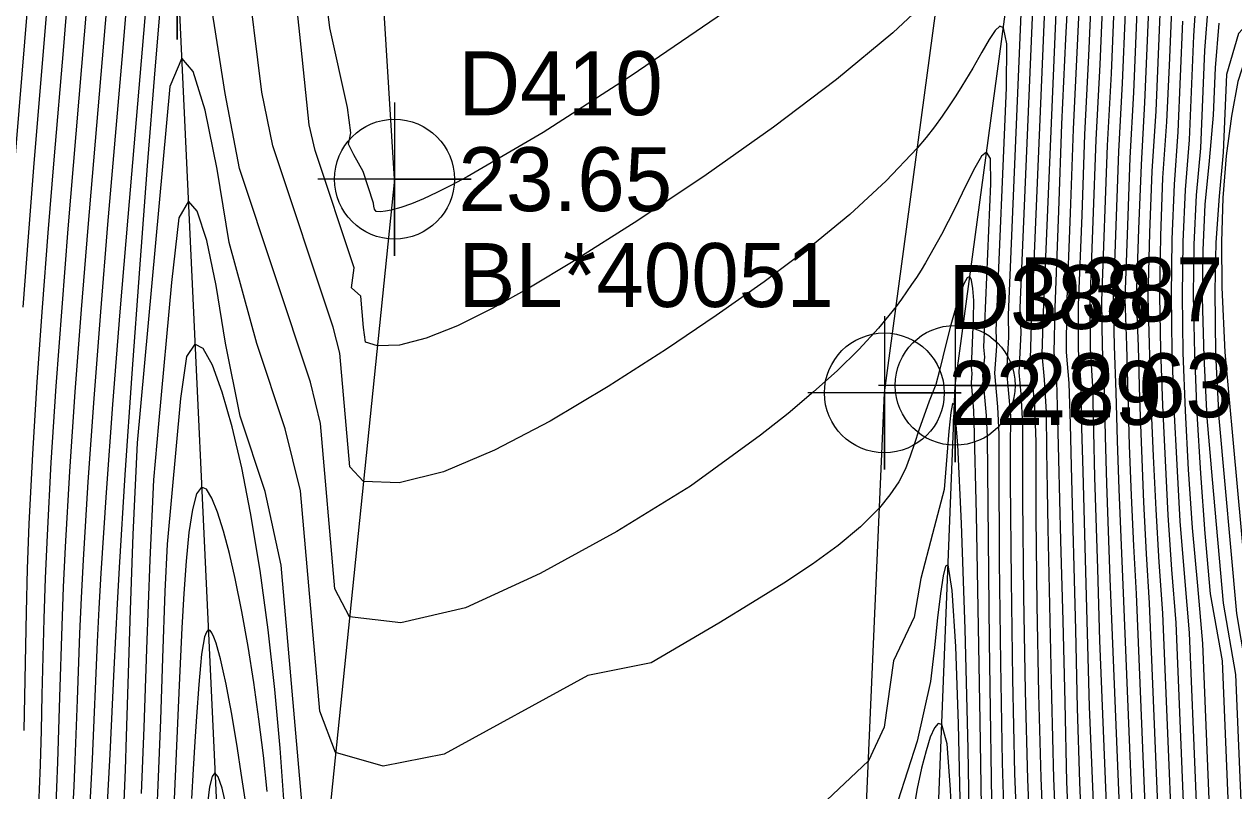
# Model space of a CAD drawing. Extents: x 2356077 to 2359823, y 225951 to 227822.
# Drawn here: x 2356540.32 to 2356587.63, y 227196.5 to 227226.48 of the extents above; entities that cross this region are included whole.
import ezdxf

# ---------------------------------------------------------------- set-up
doc = ezdxf.new("R2010")
doc.units = 0
for name, color, linetype in [('DTM Contours Major', 7, 'Continuous'), ('DTM Contours Minor', 7, 'Continuous'), ('Exist DTM Breakline', 7, 'Continuous'), ('Exist DTM Breakline Cogo Comment', 7, 'Continuous'), ('Exist DTM Breakline Cogo Elevation', 7, 'Continuous'), ('Exist DTM Breakline Cogo Number', 7, 'Continuous'), ('Exist DTM Breakline Cogo Point CELL', 7, 'Continuous'), ('Exist DTM Drainline', 7, 'Continuous'), ('Exist DTM Drainline Cogo Elevation', 7, 'Continuous'), ('Exist DTM Drainline Cogo Number', 7, 'Continuous'), ('Exist DTM Drainline Cogo Point CELL', 7, 'Continuous'), ('PH Exist DTM Breakline', 7, 'Continuous')]:
    doc.layers.add(name, color=color, linetype=linetype)

msp = doc.modelspace()

# ---------------------------------------------------------------- linework, layer by layer
at = {"layer": 'DTM Contours Major'}
for points in [[(2356580.928, 227233.104), (2356580.177, 227215.223), (2356580.125, 227213.572), (2356580.214, 227212.59), (2356580.285, 227211.313), (2356580.3, 227209.8), (2356580.324, 227208.284), (2356580.353, 227206.755), (2356580.499, 227200.164), (2356580.583, 227196.978), (2356580.991, 227187.051)], [(2356583.192, 227233.181), (2356582.829, 227224.549), (2356582.68, 227221.735), (2356582.456, 227215.663), (2356582.482, 227213.849), (2356582.554, 227212.198), (2356582.599, 227210.352), (2356582.655, 227208.511), (2356582.78, 227204.806), (2356583.105, 227196.834), (2356583.445, 227188.558)], [(2356542.236, 227230.325), (2356541.852, 227225.609), (2356541.482, 227221.178), (2356541.249, 227218.319), (2356541.023, 227215.406), (2356540.816, 227212.5), (2356540.639, 227209.659), (2356540.504, 227206.944), (2356540.439, 227205.177), (2356540.392, 227203.491), (2356540.301, 227198.856)], [(2356585.3, 227229.549), (2356585.103, 227224.873), (2356584.995, 227222.665), (2356584.843, 227220.469), (2356584.758, 227218.198), (2356584.725, 227215.861), (2356584.769, 227213.733), (2356584.841, 227211.577), (2356584.94, 227209.423), (2356585.056, 227207.276), (2356585.195, 227205.151), (2356585.364, 227203.073), (2356585.889, 227190.32)], [(2356578.194, 227194.317), (2356578.079, 227202.349), (2356578, 227210.342), (2356577.961, 227211.172), (2356577.818, 227212.745), (2356577.888, 227213.465), (2356577.859, 227213.854), (2356578.127, 227220.235), (2356578.109, 227221.233), (2356577.962, 227221.48), (2356577.765, 227221.326), (2356577.496, 227220.87), (2356577.149, 227220.168), (2356576.716, 227219.277), (2356576.192, 227218.252), (2356575.569, 227217.15), (2356575.396, 227216.865), (2356575.215, 227216.581), (2356575.028, 227216.295), (2356574.832, 227216.01), (2356574.629, 227215.726), (2356574.418, 227215.443), (2356573.727, 227214.597), (2356572.96, 227213.761), (2356572.115, 227212.93), (2356571.194, 227212.098), (2356570.196, 227211.259), (2356569.122, 227210.409), (2356566.384, 227208.411), (2356563.496, 227206.641), (2356560.499, 227204.994), (2356557.577, 227203.648), (2356555.054, 227203.071), (2356553.044, 227203.3), (2356552.465, 227204.402), (2356551.902, 227210.868), (2356551.518, 227212.478), (2356548.742, 227220.835), (2356548.174, 227223.77), (2356547.761, 227226.437), (2356547.379, 227228.812)], [(2356545.705, 227227.988), (2356545.434, 227224.703), (2356545.134, 227220.944), (2356544.825, 227216.915), (2356544.526, 227212.818), (2356544.255, 227208.855), (2356544.031, 227205.228), (2356543.953, 227203.815), (2356543.825, 227201.254), (2356543.668, 227197.932), (2356543.555, 227195.776)], [(2356589.008, 227227.424), (2356587.813, 227226.121), (2356587.349, 227224.513), (2356587.22, 227221.462), (2356587.053, 227219.76), (2356586.932, 227217.945), (2356586.884, 227216.067), (2356586.915, 227213.59), (2356587.041, 227211.067), (2356587.733, 227203.437), (2356588.228, 227200.499), (2356588.6, 227191.455)], [(2356548.957, 227196.169), (2356548.807, 227197.187), (2356548.656, 227198.158), (2356548.434, 227199.492), (2356548.323, 227200.105), (2356548.214, 227200.675), (2356548.105, 227201.194), (2356547.998, 227201.657), (2356547.91, 227201.991), (2356547.825, 227202.276), (2356547.742, 227202.506), (2356547.663, 227202.673), (2356547.588, 227202.77), (2356547.519, 227202.791), (2356547.443, 227202.708), (2356547.375, 227202.515), (2356547.314, 227202.223), (2356547.26, 227201.846), (2356547.209, 227201.396), (2356547.144, 227200.658), (2356547.054, 227199.41), (2356546.992, 227198.421), (2356546.929, 227197.348), (2356546.867, 227196.192)]]:
    msp.add_lwpolyline(points, dxfattribs=at)
at = {"layer": 'DTM Contours Minor'}
for points in [[(2356543.852, 227277.663), (2356543.291, 227273.755), (2356543.014, 227271.748), (2356542.749, 227269.703), (2356542.433, 227267.059), (2356542.174, 227264.669), (2356541.931, 227262.153), (2356541.716, 227259.564), (2356541.544, 227256.956), (2356541.428, 227254.385), (2356541.357, 227252.459), (2356541.365, 227250.684), (2356541.366, 227248.9), (2356541.392, 227243.756), (2356541.312, 227240.643), (2356541.253, 227239.098), (2356541.179, 227237.55), (2356541.09, 227235.992), (2356540.99, 227234.415), (2356540.865, 227232.636), (2356540.729, 227230.819), (2356540.429, 227227.059), (2356539.894, 227220.582)], [(2356580.51, 227233.908), (2356579.704, 227214.729), (2356579.664, 227213.409), (2356579.833, 227211.541), (2356579.883, 227210.149), (2356579.881, 227208.688), (2356579.888, 227207.219), (2356579.929, 227203.76), (2356579.986, 227200.289), (2356580.078, 227197.009), (2356580.5, 227186.773)], [(2356582.767, 227233.846), (2356582.392, 227224.908), (2356582.236, 227221.955), (2356582.001, 227215.592), (2356582.01, 227213.794), (2356582.099, 227212.312), (2356582.137, 227210.533), (2356582.186, 227208.76), (2356582.298, 227205.185), (2356582.377, 227202.383), (2356582.716, 227194.055)], [(2356583.614, 227232.485), (2356583.266, 227224.176), (2356583.125, 227221.498), (2356582.91, 227215.705), (2356582.955, 227213.886), (2356583.017, 227212.095), (2356583.07, 227210.192), (2356583.135, 227208.298), (2356583.206, 227206.404), (2356583.29, 227204.56), (2356583.933, 227188.937)], [(2356584.036, 227231.768), (2356583.702, 227223.811), (2356583.567, 227221.257), (2356583.467, 227218.612), (2356583.363, 227215.74), (2356583.429, 227213.909), (2356583.481, 227211.97), (2356583.544, 227210.002), (2356583.62, 227208.042), (2356583.702, 227206.085), (2356583.808, 227204.203), (2356584.422, 227189.273)], [(2356580.009, 227186.476), (2356579.577, 227196.955), (2356579.478, 227200.394), (2356579.418, 227204.114), (2356579.382, 227207.889), (2356579.379, 227209.345), (2356579.383, 227210.805), (2356579.313, 227212.026), (2356579.237, 227212.862), (2356579.307, 227214.412), (2356579.28, 227215.387), (2356579.938, 227231.057)], [(2356584.457, 227231.023), (2356584.138, 227223.423), (2356584.001, 227220.986), (2356583.907, 227218.469), (2356583.817, 227215.768), (2356583.892, 227213.875), (2356583.942, 227211.835), (2356584.016, 227209.806), (2356584.104, 227207.784), (2356584.197, 227205.767), (2356584.326, 227203.836), (2356584.912, 227189.617)], [(2356545.295, 227229.862), (2356544.983, 227226.121), (2356544.372, 227218.936), (2356544.065, 227215.236), (2356543.777, 227211.61), (2356543.523, 227208.164), (2356543.318, 227205.007), (2356543.241, 227203.622), (2356543.177, 227202.319), (2356542.978, 227197.74), (2356542.878, 227195.731)], [(2356567.705, 227226.948), (2356564.062, 227224.463), (2356560.611, 227222.25), (2356557.64, 227220.511), (2356557.028, 227220.185), (2356556.461, 227219.9), (2356555.941, 227219.657), (2356555.47, 227219.46), (2356555.048, 227219.309), (2356554.677, 227219.207), (2356554.457, 227219.166), (2356554.258, 227219.147), (2356554.086, 227219.154), (2356554.026, 227219.245), (2356553.996, 227219.359), (2356553.98, 227219.486), (2356553.571, 227220.719), (2356553.217, 227221.374), (2356553.003, 227221.793), (2356553.093, 227222.235), (2356552.961, 227223.221), (2356552.273, 227226.346), (2356551.833, 227229.926)], [(2356544.504, 227229.482), (2356544.135, 227225.107), (2356543.583, 227218.646), (2356543.302, 227215.237), (2356543.038, 227211.847), (2356542.806, 227208.58), (2356542.621, 227205.538), (2356542.546, 227204.051), (2356542.484, 227202.647), (2356542.387, 227200.053), (2356542.299, 227197.686), (2356542.255, 227196.685), (2356542.207, 227195.706)], [(2356581.211, 227229.087), (2356581.047, 227225.915), (2356580.892, 227222.576), (2356580.776, 227219.176), (2356580.636, 227215.387), (2356580.596, 227213.637), (2356580.696, 227212.532), (2356580.74, 227211.041), (2356580.772, 227209.47), (2356580.854, 227206.293), (2356580.942, 227203.142), (2356581.021, 227199.95), (2356581.091, 227196.85), (2356581.485, 227187.293)], [(2356578.699, 227193.831), (2356578.578, 227197.59), (2356578.513, 227201.501), (2356578.463, 227205.467), (2356578.448, 227209.367), (2356578.454, 227210.453), (2356578.406, 227211.519), (2356578.287, 227212.834), (2356578.362, 227213.893), (2356578.339, 227214.508), (2356578.737, 227223.991), (2356578.759, 227225.709), (2356578.619, 227226.345), (2356578.481, 227226.402), (2356578.298, 227226.239), (2356578.063, 227225.89), (2356577.771, 227225.387), (2356577.417, 227224.764), (2356576.997, 227224.053), (2356576.76, 227223.674), (2356576.503, 227223.283), (2356576.225, 227222.882), (2356575.924, 227222.473), (2356575.6, 227222.057), (2356575.251, 227221.637), (2356574.038, 227220.35), (2356572.614, 227219.045), (2356571.009, 227217.727), (2356569.257, 227216.405), (2356567.389, 227215.084), (2356565.437, 227213.77), (2356563.157, 227212.306), (2356560.891, 227210.956), (2356558.72, 227209.815), (2356556.725, 227208.979), (2356554.988, 227208.543), (2356553.589, 227208.602), (2356553.056, 227209.173), (2356552.67, 227213.609), (2356552.399, 227214.632), (2356550.043, 227221.725), (2356549.615, 227223.829), (2356549.006, 227228.786)], [(2356581.646, 227228.666), (2356581.346, 227222.377), (2356581.235, 227219.097), (2356581.088, 227215.386), (2356581.07, 227213.654), (2356581.181, 227212.438), (2356581.224, 227210.832), (2356581.263, 227209.182), (2356581.439, 227202.799), (2356581.504, 227199.725), (2356581.595, 227196.839), (2356581.977, 227187.557)], [(2356582.079, 227228.209), (2356581.949, 227225.25), (2356581.791, 227222.162), (2356581.681, 227219.015), (2356581.545, 227215.499), (2356581.54, 227213.73), (2356581.644, 227212.41), (2356581.677, 227210.698), (2356581.72, 227208.993), (2356581.82, 227205.554), (2356581.977, 227199.785), (2356582.465, 227187.927)], [(2356586.184, 227228.048), (2356586.056, 227226.03), (2356585.885, 227221.963), (2356585.73, 227220.005), (2356585.635, 227217.971), (2356585.606, 227215.872), (2356585.641, 227213.628), (2356585.727, 227211.354), (2356585.85, 227209.069), (2356586, 227206.788), (2356586.206, 227204.511), (2356586.404, 227202.264), (2356586.866, 227191.037)], [(2356576.084, 227227.831), (2356574.29, 227226.142), (2356572.096, 227224.325), (2356569.622, 227222.45), (2356566.99, 227220.584), (2356564.32, 227218.799), (2356561.731, 227217.163), (2356560.126, 227216.202), (2356558.629, 227215.367), (2356557.261, 227214.689), (2356556.042, 227214.199), (2356554.993, 227213.927), (2356554.133, 227213.904), (2356553.669, 227214.042), (2356553.588, 227214.616), (2356553.481, 227215.839), (2356553.119, 227216.175), (2356553.224, 227216.957), (2356551.702, 227221.537), (2356551.464, 227222.551), (2356551.154, 227225.581), (2356550.981, 227227.187)], [(2356579.513, 227186.285), (2356579.065, 227197.174), (2356578.987, 227200.882), (2356578.929, 227204.733), (2356578.899, 227208.593), (2356578.899, 227209.882), (2356578.905, 227211.165), (2356578.822, 227212.178), (2356578.758, 227212.887), (2356578.831, 227214.242), (2356578.816, 227215.111), (2356579.35, 227227.833)], [(2356584.776, 227227.851), (2356584.576, 227223.075), (2356584.427, 227220.734), (2356584.334, 227218.324), (2356584.27, 227215.807), (2356584.39, 227211.681), (2356584.477, 227209.59), (2356584.578, 227207.507), (2356584.692, 227205.443), (2356584.845, 227203.452), (2356585.4, 227189.965)], [(2356542.763, 227227.301), (2356542.028, 227218.472), (2356541.785, 227215.396), (2356541.559, 227212.326), (2356541.364, 227209.335), (2356541.213, 227206.5), (2356541.143, 227204.817), (2356541.091, 227203.219), (2356541.015, 227200.246), (2356540.981, 227198.855), (2356540.942, 227197.518), (2356540.906, 227196.553), (2356540.865, 227195.607), (2356540.818, 227194.67), (2356540.765, 227193.737), (2356540.706, 227192.799), (2356540.64, 227191.848), (2356540.434, 227189.167), (2356540.324, 227187.761), (2356540.216, 227186.305)], [(2356541.208, 227227.152), (2356540.688, 227220.881), (2356540.47, 227218.164), (2356540.261, 227215.41)], [(2356543.533, 227227.119), (2356542.805, 227218.528), (2356542.545, 227215.319), (2356542.302, 227212.107), (2356542.088, 227208.985), (2356541.92, 227206.046), (2356541.847, 227204.457), (2356541.789, 227202.953), (2356541.702, 227200.164), (2356541.62, 227197.612), (2356541.581, 227196.628), (2356541.537, 227195.664)], [(2356586.63, 227227.301), (2356586.484, 227225.451), (2356586.324, 227221.636), (2356586.162, 227219.792), (2356586.068, 227217.871), (2356586.043, 227215.879), (2356586.087, 227213.592), (2356586.19, 227211.259), (2356586.334, 227208.906), (2356586.499, 227206.559), (2356586.71, 227204.205), (2356587.177, 227201.583), (2356587.621, 227190.795)], [(2356585.628, 227226.598), (2356585.446, 227222.275), (2356585.297, 227220.209), (2356585.203, 227218.069), (2356585.176, 227215.87), (2356585.208, 227213.678), (2356585.286, 227211.468), (2356585.396, 227209.251), (2356585.525, 227207.039), (2356585.699, 227204.844), (2356585.883, 227202.68), (2356586.378, 227190.677)], [(2356587.04, 227226.516), (2356586.907, 227224.774), (2356586.829, 227222.918), (2356586.664, 227221.139), (2356586.498, 227219.431), (2356586.413, 227217.642), (2356586.398, 227215.777), (2356586.457, 227213.466), (2356586.581, 227211.092), (2356586.781, 227208.68), (2356587.22, 227203.836), (2356587.702, 227201.041), (2356588.11, 227191.125)], [(2356588.735, 227226.81), (2356588.262, 227225.693), (2356587.789, 227224.237), (2356587.541, 227222.884), (2356587.331, 227221.329), (2356587.205, 227219.688), (2356587.153, 227217.971), (2356587.162, 227216.187), (2356587.282, 227213.652), (2356588.238, 227203.117), (2356588.753, 227199.957), (2356589.09, 227191.785)], [(2356577.774, 227195.042), (2356577.711, 227199.219), (2356577.568, 227207.321), (2356577.472, 227210.939), (2356577.467, 227211.358), (2356577.367, 227212.472), (2356577.4, 227212.824), (2356577.375, 227213.086), (2356577.453, 227214.947), (2356577.456, 227215.669), (2356577.424, 227216.15), (2356577.376, 227216.469), (2356577.306, 227216.614), (2356577.2, 227216.567), (2356577.068, 227216.322), (2356576.914, 227215.912), (2356576.745, 227215.368), (2356576.566, 227214.722), (2356576.382, 227214.005), (2356576.121, 227212.94), (2356575.981, 227212.389), (2356575.717, 227211.737), (2356575.308, 227210.6), (2356575.141, 227210.084), (2356574.973, 227209.583), (2356574.786, 227209.09), (2356574.523, 227208.584), (2356574.174, 227208.071), (2356573.768, 227207.568), (2356573.031, 227206.825), (2356572.154, 227206.094), (2356571.15, 227205.364), (2356570.029, 227204.622), (2356568.802, 227203.857), (2356567.482, 227203.057), (2356564.844, 227201.509), (2356562.362, 227201.014), (2356556.739, 227197.925), (2356554.361, 227197.466), (2356552.5, 227197.998), (2356551.876, 227199.609), (2356551.125, 227208.23), (2356550.526, 227210.657), (2356549.418, 227213.993), (2356548.331, 227217.942), (2356547.87, 227220.818), (2356547.394, 227223.12), (2356546.923, 227224.634), (2356546.479, 227225.147), (2356546.009, 227224.045), (2356544.738, 227210.114), (2356544.57, 227206.517), (2356544.467, 227203.562), (2356544.31, 227198.625), (2356544.262, 227197.316), (2356544.211, 227196.086)], [(2356551.295, 227194.728), (2356550.372, 227205.324), (2356549.744, 227208.205), (2356548.765, 227211.153), (2356548.196, 227214.011), (2356547.832, 227216.259), (2356547.456, 227218.022), (2356547.086, 227219.166), (2356546.739, 227219.558), (2356546.366, 227218.912), (2356546.079, 227216.376), (2356545.575, 227210.849), (2356545.379, 227208.657), (2356545.238, 227205.536), (2356545.106, 227202.038), (2356544.997, 227198.977), (2356544.89, 227196.395)], [(2356550.485, 227195.977), (2356550.329, 227198.168), (2356550.122, 227200.456), (2356549.862, 227202.788), (2356549.547, 227205.109), (2356549.174, 227207.366), (2356548.825, 227209.127), (2356548.45, 227210.729), (2356548.065, 227212.093), (2356547.684, 227213.14), (2356547.324, 227213.792), (2356546.999, 227213.969), (2356546.667, 227213.481), (2356546.435, 227211.844), (2356545.916, 227206.148), (2356545.814, 227204.291), (2356545.724, 227201.686), (2356545.645, 227199.273), (2356545.549, 227196.719), (2356545.388, 227193.065)], [(2356577.324, 227193.358), (2356577.238, 227198.135), (2356577.121, 227202.824), (2356576.985, 227206.947), (2356576.841, 227210.024), (2356576.701, 227211.577), (2356576.634, 227211.652), (2356576.566, 227211.29), (2356576.49, 227210.56), (2356576.299, 227208.279), (2356575.85, 227206.544), (2356575.39, 227204.806), (2356575.124, 227203.295), (2356574.315, 227201.577), (2356573.961, 227198.984), (2356573.337, 227197.672), (2356571.477, 227195.905)], [(2356549.826, 227196.477), (2356549.673, 227197.875), (2356549.496, 227199.303), (2356549.296, 227200.736), (2356549.075, 227202.146), (2356548.835, 227203.509), (2356548.575, 227204.797), (2356548.348, 227205.779), (2356548.116, 227206.656), (2356547.884, 227207.392), (2356547.66, 227207.949), (2356547.449, 227208.291), (2356547.259, 227208.38), (2356547.061, 227208.119), (2356546.897, 227207.5), (2356546.763, 227206.596), (2356546.654, 227205.477), (2356546.564, 227204.212), (2356546.49, 227202.875), (2356546.386, 227200.636), (2356546.006, 227192.009)], [(2356576.94, 227195.579), (2356576.862, 227199.111), (2356576.755, 227202.144), (2356576.62, 227204.333), (2356576.455, 227205.331), (2356576.36, 227205.288), (2356576.259, 227204.9), (2356576.152, 227204.21), (2356576.04, 227203.264), (2356575.923, 227202.107), (2356575.773, 227200.768), (2356575.252, 227198.434), (2356574.49, 227196.097)], [(2356576.645, 227194.362), (2356576.555, 227196.544), (2356576.422, 227198.335), (2356576.209, 227199.086), (2356576.073, 227199.129), (2356575.922, 227198.957), (2356575.76, 227198.593), (2356575.592, 227198.061), (2356575.421, 227197.383), (2356575.252, 227196.584), (2356574.964, 227194.897)], [(2356548.214, 227195.912), (2356548.057, 227196.602), (2356547.91, 227197.043), (2356547.779, 227197.202), (2356547.667, 227197.063), (2356547.569, 227196.652), (2356547.485, 227195.995)]]:
    msp.add_lwpolyline(points, dxfattribs=at)
at = {"layer": 'Exist DTM Breakline'}
for points in [[(2356575.82, 227148.639), (2356572.681, 227182.58), (2356573.963, 227212.061), (2356577.748, 227240.207), (2356581.287, 227243.662), (2356587.377, 227239.444), (2356592.648, 227232.822), (2356591.439, 227218.21), (2356593.678, 227194.877), (2356594.225, 227153.117)], [(2356554.802, 227220.421), (2356551.682, 227190.031), (2356554.693, 227150.844), (2356559.046, 227114.057), (2356563.68, 227075.466), (2356576.505, 227009.716)]]:
    msp.add_lwpolyline(points, dxfattribs=at)
at = {"layer": 'Exist DTM Breakline Cogo Point CELL'}
for points in [[(2356554.802, 227223.421), (2356554.802, 227217.421), (2356554.802, 227220.421), (2356557.802, 227220.421), (2356551.802, 227220.421)], [(2356573.963, 227215.061), (2356573.963, 227209.061), (2356573.963, 227212.061), (2356576.963, 227212.061), (2356570.963, 227212.061)]]:
    msp.add_lwpolyline(points, dxfattribs=at)
for centre in [(2356554.802, 227220.421), (2356573.963, 227212.061)]:
    msp.add_circle(centre, 2.344, dxfattribs=at)
at = {"layer": 'Exist DTM Drainline'}
for points in [[(2356548.776, 227304.309), (2356547.572, 227273.186), (2356546.306, 227228.878), (2356548.057, 227191.22), (2356550.765, 227150.688), (2356554.732, 227113.271), (2356560.954, 227074.926), (2356573.805, 227008.735)], [(2356578.049, 227148.523), (2356575.562, 227182.67), (2356576.732, 227212.357), (2356580.297, 227238.787)]]:
    msp.add_lwpolyline(points, dxfattribs=at)
at = {"layer": 'Exist DTM Drainline Cogo Point CELL'}
for points in [[(2356546.306, 227231.878), (2356546.306, 227225.878), (2356546.306, 227228.878), (2356549.306, 227228.878), (2356543.306, 227228.878)], [(2356576.732, 227215.357), (2356576.732, 227209.357), (2356576.732, 227212.357), (2356579.732, 227212.357), (2356573.732, 227212.357)]]:
    msp.add_lwpolyline(points, dxfattribs=at)
msp.add_circle((2356576.732, 227212.357), 2.344, dxfattribs=at)
at = {"layer": 'PH Exist DTM Breakline'}
msp.add_lwpolyline([(2356554.802, 227220.421), (2356552.964, 227250.065), (2356554.762, 227266.989), (2356558.085, 227280.739), (2356558.431, 227290.839), (2356559.137, 227302.225), (2356558.722, 227311.603), (2356557.308, 227318.008), (2356555.736, 227323.861), (2356552.945, 227329.698)], dxfattribs=at)

# ---------------------------------------------------------------- texts
at = {"layer": 'Exist DTM Breakline Cogo Comment'}
msp.add_text('BL*40051', height=2.5, dxfattribs=at).set_placement((2356557.302, 227215.421))
at = {"layer": 'Exist DTM Breakline Cogo Elevation'}
for s, p in [('23.65', (2356557.302, 227219.171)), ('22.89', (2356576.463, 227210.811))]:
    msp.add_text(s, height=2.5, dxfattribs=at).set_placement(p)
at = {"layer": 'Exist DTM Breakline Cogo Number'}
for s, p in [('D410', (2356557.302, 227222.921)), ('D388', (2356576.463, 227214.561))]:
    msp.add_text(s, height=2.5, dxfattribs=at).set_placement(p)
at = {"layer": 'Exist DTM Drainline Cogo Elevation'}
msp.add_text('22.63', height=2.5, dxfattribs=at).set_placement((2356579.232, 227211.108))
at = {"layer": 'Exist DTM Drainline Cogo Number'}
msp.add_text('D387', height=2.5, dxfattribs=at).set_placement((2356579.232, 227214.858))

doc.saveas('drawing.dxf')
